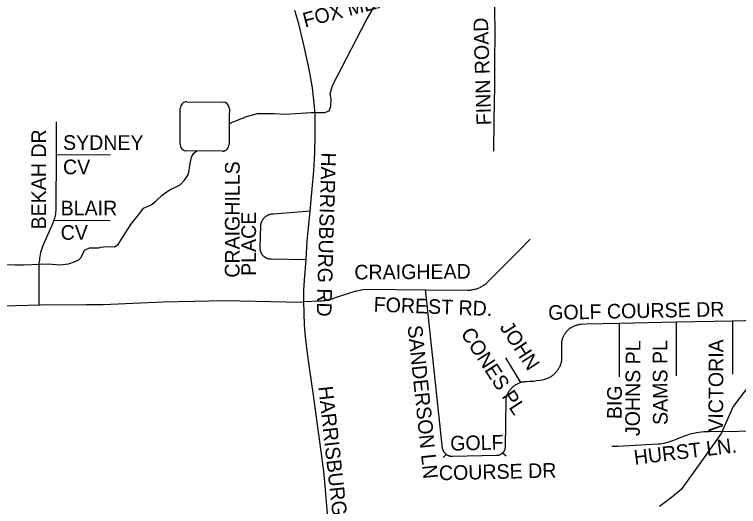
# Model space of a CAD drawing. Extents: x 1670563 to 1761545, y 515755 to 578944.
# Drawn here: x 1700311 to 1704021, y 529948 to 532470 of the extents above; entities that cross this region are included whole.
import ezdxf

# ---------------------------------------------------------------- set-up
doc = ezdxf.new("R2010")
doc.units = 0
for name, color, linetype in [('SHP_LINE', 7, 'Continuous'), ('STREETCL', 7, 'Continuous'), ('STRNAMES', 7, 'Continuous')]:
    doc.layers.add(name, color=color, linetype=linetype)

msp = doc.modelspace()

# ---------------------------------------------------------------- linework, layer by layer
at = {"layer": 'SHP_LINE'}
for points in [[(1701419, 531915), (1701500, 531946), (1701557, 531962), (1701642, 531962), (1701699, 531959), (1701832, 531967), (1701901, 531967), (1701923, 531976), (1701932, 531998), (1701934, 532035), (1701929, 532063), (1701941, 532105), (1702114, 532438), (1702182, 532558), (1702229, 532681), (1702264, 532734), (1702397, 532968), (1702467, 533088), (1702571, 533261), (1702664, 533427), (1702778, 533665), (1702788, 533697), (1702807, 533763), (1702831, 533823)], [(1701195.1, 532022.1), (1701378.6, 532020.9)], [(1701159.7, 531804.9), (1701160.9, 531988.4)], [(1701412.4, 531986.6), (1701412.1, 531946.4), (1701412, 531926.4), (1701411.1, 531803.2)], [(1701411.9, 531910.1), (1701419, 531915)], [(1700248, 531189), (1700315, 531187), (1700357, 531187), (1700485, 531191), (1700544, 531186), (1700589, 531191), (1700617, 531202), (1700641, 531213), (1700654, 531227), (1700670, 531262), (1700696, 531274), (1700710, 531273), (1700743, 531273), (1700754, 531278), (1700785, 531281), (1700824, 531279), (1700843, 531291), (1700877, 531346), (1700907, 531393), (1700954, 531451), (1700973, 531477), (1701012, 531494), (1701036, 531513), (1701068, 531544), (1701104, 531569), (1701161, 531596), (1701183, 531621), (1701203, 531652), (1701212, 531706), (1701218, 531738), (1701230, 531759), (1701246.3, 531770.3)], [(1701376.9, 531769.4), (1701193.4, 531770.6)], [(1706719, 530758), (1706639, 530778), (1705509, 530715), (1705410, 530703), (1705320, 530688), (1705208, 530676), (1704934, 530686), (1704685, 530667), (1704350, 530676), (1704212, 530671), (1704175, 530661), (1704138, 530634), (1704078, 530573), (1703994, 530461), (1703932, 530323), (1703828, 530175), (1703727, 530036), (1703677, 529995), (1703616, 529948)]]:
    msp.add_lwpolyline(points, dxfattribs=at)
for centre, start, end in [((1701194.9, 531988.1), 89.6126, 179.6127), ((1701378.4, 531986.9), 359.6127, 89.6126), ((1701193.7, 531804.6), 179.6127, 269.6126), ((1701377.1, 531803.4), 269.6126, 359.6127)]:
    msp.add_arc(centre, 34, start, end, dxfattribs=at)
at = {"layer": 'STREETCL'}
for p, q in [((1700526.7, 531751.6), (1700803.5, 531750.6)), ((1700514.5, 531415.7), (1700802.2, 531414.6))]:
    msp.add_line(p, q, dxfattribs=at)
for points in [[(1702769.7, 532661.1), (1702771.1, 532521.7), (1702772, 532352.2), (1702770.8, 532249.2), (1702771, 532103.2), (1702766.6, 531927.8), (1702766.3, 531768.8)], [(1701826.1, 531462), (1701837, 531577), (1701844.6, 531669), (1701849.7, 531761.2), (1701852.5, 531853.5), (1701852.5, 531901.7), (1701851.1, 531950), (1701848.2, 531998.1), (1701843.8, 532046.1), (1701837.8, 532094), (1701830.5, 532141.7), (1701821.6, 532189.1), (1701796.3, 532306), (1701768, 532422.2), (1701758.6, 532456.5), (1701748.1, 532490.6)], [(1700525.6, 531480.7), (1700526.7, 531751.6), (1700527.3, 531919.6)], [(1701826.1, 531462), (1701637.7, 531447.1), (1701635.4, 531447), (1701633, 531446.8), (1701630.7, 531446.6), (1701628.3, 531446.3), (1701626, 531445.9), (1701623.7, 531445.4), (1701621.4, 531444.9), (1701619.1, 531444.2), (1701616.9, 531443.5), (1701614.6, 531442.7), (1701612.4, 531441.9), (1701610.3, 531440.9), (1701608.2, 531439.9), (1701606.1, 531438.8), (1701604, 531437.6), (1701602, 531436.4), (1701600, 531435.1), (1701598.1, 531433.7), (1701596.2, 531432.3), (1701594.4, 531430.7), (1701592.7, 531429.2), (1701591, 531427.5), (1701589.3, 531425.9), (1701587.7, 531424.1), (1701586.2, 531422.3), (1701584.7, 531420.5), (1701583.3, 531418.6), (1701582, 531416.6), (1701580.7, 531414.6), (1701579.5, 531412.6), (1701578.4, 531410.5), (1701577.4, 531408.4), (1701576.4, 531406.2), (1701575.5, 531404), (1701574.7, 531401.8), (1701573.9, 531399.6), (1701573.3, 531397.3), (1701572.7, 531395), (1701572.2, 531392.7), (1701571.8, 531390.4), (1701571.4, 531388.1), (1701568.7, 531273.7), (1701568.7, 531271.7), (1701568.8, 531269.8), (1701568.9, 531267.9), (1701569.1, 531266), (1701569.4, 531264.1), (1701569.7, 531262.2), (1701570.1, 531260.3), (1701570.6, 531258.4), (1701571.1, 531256.6), (1701571.7, 531254.7), (1701572.4, 531252.9), (1701573.1, 531251.1), (1701573.9, 531249.4), (1701574.8, 531247.6), (1701575.7, 531245.9), (1701576.6, 531244.3), (1701577.7, 531242.6), (1701578.7, 531241), (1701579.9, 531239.5), (1701581.1, 531237.9), (1701582.3, 531236.5), (1701583.6, 531235), (1701584.9, 531233.6), (1701586.3, 531232.3), (1701587.7, 531231), (1701589.2, 531229.8), (1701590.7, 531228.6), (1701592.3, 531227.4), (1701593.9, 531226.4), (1701595.5, 531225.3), (1701597.2, 531224.4), (1701598.9, 531223.4), (1701600.6, 531222.6), (1701602.4, 531221.8), (1701604.2, 531221.1), (1701606, 531220.4), (1701607.8, 531219.8), (1701609.7, 531219.3), (1701611.5, 531218.8), (1701613.4, 531218.4), (1701615.3, 531218), (1701617.2, 531217.8), (1701619.1, 531217.6), (1701621.1, 531217.4), (1701623, 531217.3), (1701624.9, 531217.3), (1701626.8, 531217.4), (1701805.4, 531213.4)], [(1701805.4, 531213.4), (1701811.6, 531308.7), (1701826.1, 531462)], [(1700455.3, 531278.9), (1700508.9, 531401.3)], [(1702417.1, 531059.1), (1702634.4, 531057.4), (1702639.4, 531057.4), (1702644.3, 531057.7), (1702649.2, 531058.1), (1702654.1, 531058.7), (1702659, 531059.5), (1702663.9, 531060.4), (1702668.7, 531061.5), (1702673.5, 531062.7), (1702678.2, 531064.1), (1702682.9, 531065.7), (1702687.5, 531067.4), (1702692.1, 531069.3), (1702696.6, 531071.3), (1702701, 531073.5), (1702705.4, 531075.9), (1702709.6, 531078.4), (1702713.8, 531081), (1702717.9, 531083.8), (1702721.9, 531086.7), (1702725.8, 531089.7), (1702729.6, 531092.9), (1702733.2, 531096.2), (1702900.4, 531263.3), (1702953.4, 531318.3)], [(1700437.7, 530981.8), (1700438.6, 531199.5)], [(1701793.5, 530999.2), (1701793.4, 531030.4), (1701794, 531056.4), (1701795.2, 531082.4), (1701797.1, 531108.4), (1701805.4, 531213.4)], [(1701793.5, 530999.2), (1701878.1, 531002.4), (1701886.1, 531002.8), (1701894, 531003.5), (1701901.9, 531004.5), (1701909.7, 531005.7), (1701917.6, 531007.2), (1701925.3, 531009), (1701933, 531011), (1701940.6, 531013.3), (1701948.1, 531015.8), (1701955.6, 531018.7), (1702035.1, 531045.1), (1702047.1, 531048.9), (1702059.2, 531052.3), (1702071.4, 531055.2), (1702083.7, 531057.7), (1702096, 531059.8), (1702108.5, 531061.4), (1702417.1, 531059.1)], [(1702522.7, 530215.6), (1702521.4, 530216.7), (1702520.1, 530217.9), (1702518.9, 530219), (1702517.7, 530220.3), (1702516.5, 530221.6), (1702515.4, 530222.9), (1702514.3, 530224.2), (1702513.3, 530225.6), (1702512.3, 530227), (1702511.4, 530228.5), (1702510.5, 530229.9), (1702509.7, 530231.5), (1702508.9, 530233), (1702508.2, 530234.5), (1702507.5, 530236.1), (1702506.9, 530237.7), (1702506.3, 530239.4), (1702505.8, 530241), (1702505.3, 530242.7), (1702504.9, 530244.3), (1702504.6, 530246), (1702449.7, 530758.8), (1702417.1, 531059.9)], [(1699791.5, 530960.5), (1699809.8, 530960.9), (1700124.5, 530972.4), (1700444.8, 530982.1), (1700680, 530983.8), (1700765.8, 530983.2), (1701072.3, 530997.3), (1701389.5, 531004.5), (1701704, 530996.9), (1701793.5, 530994.9)], [(1701945.6, 529660.9), (1701940.6, 529685.9), (1701936.3, 529711.1), (1701932.8, 529736.3), (1701930.1, 529761.7), (1701928.1, 529787.1), (1701912.7, 529931.5), (1701902.7, 530054.6), (1701895.5, 530130.1), (1701886.3, 530205.3), (1701843.6, 530518.1), (1701822.5, 530659.4), (1701808.9, 530760.2), (1701802.5, 530819.8), (1701797.8, 530879.5), (1701794.8, 530939.3), (1701793.5, 530999.2)], [(1703990, 530898.4), (1703700.8, 530892.2)], [(1704181.4, 530902.5), (1703990, 530898.4)], [(1703990, 530898.4), (1703990, 530626)], [(1703410.1, 530886), (1703240.2, 530882.4), (1703213.8, 530880.7), (1703210.2, 530880.5), (1703206.5, 530880.1), (1703202.9, 530879.6), (1703199.2, 530879), (1703195.7, 530878.3), (1703192.1, 530877.4), (1703188.6, 530876.4), (1703185.1, 530875.3), (1703181.6, 530874.1), (1703178.2, 530872.7), (1703174.8, 530871.3), (1703171.5, 530869.7), (1703168.2, 530868), (1703165.1, 530866.2), (1703161.9, 530864.3), (1703158.9, 530862.2), (1703155.9, 530860.1), (1703153, 530857.9), (1703150.1, 530855.5), (1703147.4, 530853.1), (1703144.7, 530850.6), (1703142.2, 530847.9), (1703139.7, 530845.2), (1703137.3, 530842.4), (1703135, 530839.6), (1703132.8, 530836.6), (1703130.8, 530833.6), (1703128.8, 530830.5), (1703126.9, 530827.3), (1703125.2, 530824.1), (1703123.5, 530820.8), (1703122, 530817.5), (1703120.6, 530814.1), (1703119.3, 530810.6), (1703118.2, 530807.2), (1703117.1, 530803.6), (1703116.2, 530800.1), (1703115.4, 530796.5), (1703114.7, 530792.9), (1703114.2, 530789.3), (1703113.8, 530785.6), (1703113.5, 530782), (1703113.3, 530778.3), (1703113.3, 530774.6), (1703113.4, 530771), (1703113.3, 530694.1), (1703112.5, 530690), (1703111.5, 530686), (1703110.4, 530682), (1703109.2, 530678), (1703107.9, 530674.1), (1703106.4, 530670.2), (1703104.7, 530666.3), (1703103, 530662.6), (1703101.1, 530658.9), (1703099.1, 530655.2), (1703096.9, 530651.7), (1703094.7, 530648.2), (1703092.3, 530644.7), (1703089.8, 530641.4), (1703087.2, 530638.2), (1703084.5, 530635), (1703081.7, 530631.9), (1703078.8, 530629), (1703075.8, 530626.1), (1703072.7, 530623.4), (1703069.5, 530620.7), (1703066.2, 530618.2), (1703062.8, 530615.7), (1703059.3, 530613.4), (1703055.8, 530611.2), (1703052.2, 530609.2), (1703048.5, 530607.2), (1703044.8, 530605.4), (1703041, 530603.7), (1703037.1, 530602.1), (1703033.2, 530600.7), (1703029.2, 530599.4), (1703025.3, 530598.3), (1703021.2, 530597.2), (1703004.4, 530594.1), (1702987.4, 530591.6), (1702970.4, 530589.7), (1702953.3, 530588.4), (1702936.2, 530587.7), (1702932.7, 530587.7), (1702929.1, 530587.5), (1702925.6, 530587.2), (1702922, 530586.8), (1702918.5, 530586.2), (1702915, 530585.6), (1702911.5, 530584.8), (1702908.1, 530584), (1702904.6, 530583)], [(1703700.8, 530892.2), (1703410.1, 530886)], [(1703410.1, 530886), (1703410.1, 530612.8)], [(1703700.8, 530892.2), (1703700.8, 530618.7)], [(1702827.5, 530710.7), (1702904.6, 530583)], [(1702904.6, 530583), (1702901, 530581.8), (1702897.4, 530580.5), (1702893.9, 530579.1), (1702890.4, 530577.6), (1702886.9, 530575.9), (1702883.6, 530574.1), (1702880.2, 530572.3), (1702877, 530570.2), (1702873.8, 530568.1), (1702870.7, 530565.9), (1702867.7, 530563.6), (1702864.8, 530561.1), (1702861.9, 530558.6), (1702859.2, 530556), (1702856.5, 530553.2), (1702853.9, 530550.4), (1702851.4, 530547.5), (1702849.1, 530544.5), (1702846.8, 530541.5), (1702844.6, 530538.3), (1702842.6, 530535.1), (1702840.6, 530531.8), (1702838.8, 530528.5), (1702837.1, 530525), (1702835.5, 530521.6), (1702834.1, 530518), (1702832.7, 530514.5), (1702831.5, 530510.9), (1702830.4, 530507.2), (1702829.4, 530503.5), (1702828.6, 530499.8), (1702827.9, 530496), (1702824.7, 530252.5), (1702824.6, 530251), (1702824.5, 530249.5), (1702824.4, 530248), (1702824.2, 530246.5), (1702823.9, 530245), (1702823.6, 530243.5), (1702823.3, 530242.1), (1702822.9, 530240.6), (1702822.4, 530239.2), (1702821.9, 530237.7), (1702821.3, 530236.3), (1702820.7, 530234.9), (1702820.1, 530233.6), (1702819.4, 530232.2), (1702818.7, 530230.9), (1702817.9, 530229.6), (1702817.1, 530228.3), (1702816.2, 530227.1), (1702815.3, 530225.9), (1702814.3, 530224.7), (1702813.3, 530223.6), (1702812.3, 530222.5)], [(1704176.5, 530335.1), (1703870.6, 530331.4), (1703857.5, 530331), (1703844.4, 530330.2), (1703831.3, 530329), (1703818.3, 530327.3), (1703805.4, 530325.3), (1703792.5, 530322.8), (1703779.7, 530319.9), (1703767, 530316.5), (1703754.4, 530312.8), (1703741.9, 530308.6), (1703729.6, 530304.1), (1703717.5, 530299.1), (1703705.5, 530293.8), (1703696.3, 530289.7), (1703687, 530285.9), (1703677.5, 530282.4), (1703667.9, 530279.3), (1703658.3, 530276.4), (1703648.5, 530274), (1703638.7, 530271.8), (1703628.8, 530270), (1703618.8, 530268.5), (1703608.8, 530267.4), (1703403.2, 530255.7), (1703371.2, 530255.7)], [(1702522.7, 530215.6), (1702508.2, 530199.8)], [(1702812.3, 530222.5), (1702811.2, 530221.4), (1702810.1, 530220.4), (1702809, 530219.4), (1702807.8, 530218.4), (1702806.6, 530217.5), (1702805.4, 530216.6), (1702804.1, 530215.8), (1702802.8, 530215), (1702801.5, 530214.3), (1702800.2, 530213.6), (1702798.8, 530212.9), (1702797.4, 530212.3), (1702796, 530211.7), (1702794.6, 530211.2), (1702793.1, 530210.8), (1702791.7, 530210.4), (1702790.2, 530210), (1702788.7, 530209.7), (1702787.2, 530209.5), (1702785.7, 530209.2), (1702784.2, 530209.1), (1702782.7, 530209), (1702556.2, 530204.1), (1702554.5, 530204.1), (1702552.8, 530204.1), (1702551, 530204.3), (1702549.3, 530204.4), (1702547.6, 530204.6), (1702545.9, 530204.9), (1702544.2, 530205.3), (1702542.6, 530205.6), (1702540.9, 530206.1), (1702539.3, 530206.6), (1702537.6, 530207.2), (1702536, 530207.8), (1702534.4, 530208.4), (1702532.9, 530209.2), (1702531.3, 530209.9), (1702529.8, 530210.7), (1702528.3, 530211.6), (1702526.9, 530212.5), (1702525.4, 530213.5), (1702524.1, 530214.5), (1702522.7, 530215.6)], [(1702812.3, 530222.5), (1702830.3, 530208)]]:
    msp.add_lwpolyline(points, dxfattribs=at)
for centre, start, end in [((1700325.6, 531481.5), 340.7815, 359.7813), ((1700325.6, 531481.5), 336.3753, 340.7815), ((1700638.6, 531198.8), 156.3753, 179.7813)]:
    msp.add_arc(centre, 200, start, end, dxfattribs=at)

# ---------------------------------------------------------------- texts
at = {"layer": 'STRNAMES'}
for s, rotation, p in [('FOX MEADOW LN.', 14.5702, (1701799.7, 532402.8)), ('FINN ROAD', 91.8032, (1702754.1, 531903.1)), ('BEKAH DR', 90, (1700473.2, 531368.2)), ('HARRISBURG RD', 268.3537, (1701883.8, 531763.3)), ('CRAIGHILLS', 89.9209, (1701464.4, 531120.8)), (' PLACE', 89.9209, (1701548.5, 531102.2)), ('CRAIGHEAD', 0.4227, (1702053, 531111.7)), ('FOREST RD.', 357.8366, (1702150.8, 530947.3)), ('GOLF COURSE DR', 1.1521, (1703046.6, 530904.6)), ('SANDERSON LN', 275.9792, (1702325.2, 530873.5)), ('CONES PL', 303.1187, (1702595, 530835)), ('JOHN ', 303.1187, (1702795, 530866.8)), ('JOHNS PL', 89.5895, (1703515.2, 530308.8)), ('SAMS PL', 90.3133, (1703657.9, 530366.3)), ('VICTORIA ', 89.6842, (1703941.3, 530331.4)), ('HARRISBURG RD ', 276.3248, (1701867.7, 530561.5)), ('BIG ', 89.5895, (1703422.3, 530395.9)), ('GOLF ', 1.3314, (1702544.6, 530234.4)), ('HURST LN.', 6.9929, (1703489.5, 530161.7)), ('COURSE DR', 1.3314, (1702486.8, 530082.7))]:
    msp.add_text(s, height=75, rotation=rotation, dxfattribs=at).set_placement(p)
for s, p in [('SYDNEY ', (1700560.2, 531776)), ('CV', (1700560.2, 531651)), ('BLAIR ', (1700548, 531440.1)), ('CV', (1700548, 531315.1))]:
    msp.add_text(s, height=75, dxfattribs=at).set_placement(p)

doc.saveas('drawing.dxf')
